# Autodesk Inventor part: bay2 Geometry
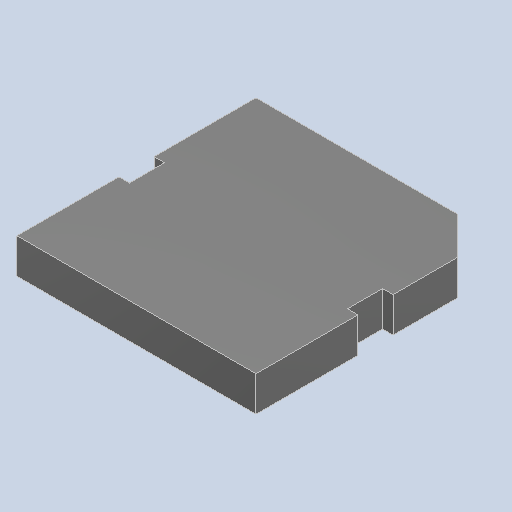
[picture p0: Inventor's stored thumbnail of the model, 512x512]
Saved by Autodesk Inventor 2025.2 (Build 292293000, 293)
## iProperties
Created: 2025-04
Part Number: bay2 Geometry
Material: Generic
Description: PART-bay2 Geometry-DESC
Document SubType Name: Modeling
Designer: BennF
Density: 1 g/cm^3
Appearance: Default
Author: BennF
Revision Number: NONE
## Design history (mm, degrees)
feature "bay"
body "Solid1"
